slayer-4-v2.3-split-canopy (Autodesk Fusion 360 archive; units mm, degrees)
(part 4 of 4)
sketch "GEMFAN" plane through (28.9566, 10, -18.6867) normal (0, 1, 0) x axis (1, 0, 0)
  line L1 (-18.7002, -15.1005) -> (-18.9977, -15.145)
  curve K1 (-18.6889, -15.209) -> (-18.7002, -15.1005)
  curve K2 (-18.5682, -15.2594) -> (-18.6889, -15.209)
  curve K3 (-18.4588, -15.2187) -> (-18.5682, -15.2594)
  curve K4 (-18.4051, -15.1417) -> (-18.4588, -15.2187)
  curve K5 (-18.4216, -15.0733) -> (-18.4051, -15.1417)
  curve K6 (-18.5646, -15.0277) -> (-18.4216, -15.0733)
  curve K7 (-18.8229, -14.9284) -> (-18.5646, -15.0277)
  curve K8 (-18.8613, -14.738) -> (-18.8229, -14.9284)
  curve K9 (-18.7802, -14.5847) -> (-18.8613, -14.738)
  curve K10 (-18.6193, -14.4624) -> (-18.7802, -14.5847)
  curve K11 (-18.3644, -14.4007) -> (-18.6193, -14.4624)
  curve K12 (-18.0912, -14.4484) -> (-18.3644, -14.4007)
  curve K13 (-18.0289, -14.6706) -> (-18.0912, -14.4484)
  line L2 (-18.3234, -14.7135) -> (-18.0289, -14.6706)
  curve K14 (-18.3473, -14.617) -> (-18.3234, -14.7135)
  curve K15 (-18.4418, -14.5944) -> (-18.3473, -14.617)
  curve K16 (-18.5284, -14.625) -> (-18.4418, -14.5944)
  curve K17 (-18.5696, -14.6844) -> (-18.5284, -14.625)
  curve K18 (-18.558, -14.7265) -> (-18.5696, -14.6844)
  curve K19 (-18.4639, -14.7552) -> (-18.558, -14.7265)
  curve K20 (-18.197, -14.8206) -> (-18.4639, -14.7552)
  curve K21 (-18.0978, -14.9231) -> (-18.197, -14.8206)
  curve K22 (-18.0953, -15.0715) -> (-18.0978, -14.9231)
  curve K23 (-18.1929, -15.2581) -> (-18.0953, -15.0715)
  curve K24 (-18.3719, -15.3973) -> (-18.1929, -15.2581)
  curve K25 (-18.6224, -15.4614) -> (-18.3719, -15.3973)
  curve K26 (-18.9497, -15.3914) -> (-18.6224, -15.4614)
  curve K27 (-18.9977, -15.145) -> (-18.9497, -15.3914)
  line L3 (-17.4629, -14.339) -> (-17.7707, -14.3659)
  line L4 (-17.6524, -15.1122) -> (-17.4629, -14.339)
  line L5 (-17.172, -15.0702) -> (-17.6524, -15.1122)
  line L6 (-17.2339, -15.3228) -> (-17.172, -15.0702)
  line L7 (-18.0221, -15.3917) -> (-17.2339, -15.3228)
  line L8 (-17.7707, -14.3659) -> (-18.0221, -15.3917)
  line L9 (-16.7894, -15.1182) -> (-16.4399, -15.0876)
  line L10 (-16.8795, -15.2918) -> (-16.7894, -15.1182)
  line L11 (-17.1938, -15.3193) -> (-16.8795, -15.2918)
  line L12 (-16.568, -14.2607) -> (-17.1938, -15.3193)
  line L13 (-16.2322, -14.2313) -> (-16.568, -14.2607)
  line L14 (-16.1092, -15.2244) -> (-16.2322, -14.2313)
  line L15 (-16.4316, -15.2526) -> (-16.1092, -15.2244)
  line L16 (-16.4399, -15.0876) -> (-16.4316, -15.2526)
  line L17 (-16.469, -14.5122) -> (-16.4494, -14.8714)
  line L18 (-16.6682, -14.8905) -> (-16.469, -14.5122)
  line L19 (-16.4494, -14.8714) -> (-16.6682, -14.8905)
  line L20 (-15.6369, -14.1792) -> (-15.9788, -14.2091)
  line L21 (-15.521, -14.5077) -> (-15.6369, -14.1792)
  line L22 (-15.235, -14.1441) -> (-15.521, -14.5077)
  line L23 (-14.895, -14.1143) -> (-15.235, -14.1441)
  line L24 (-15.4284, -14.7444) -> (-14.895, -14.1143)
  line L25 (-15.5337, -15.174) -> (-15.4284, -14.7444)
  line L26 (-15.8422, -15.201) -> (-15.5337, -15.174)
  line L27 (-15.7369, -14.7714) -> (-15.8422, -15.201)
  line L28 (-15.9788, -14.2091) -> (-15.7369, -14.7714)
  line L29 (-13.9715, -14.0335) -> (-14.7964, -14.1057)
  line L30 (-14.0251, -14.2525) -> (-13.9715, -14.0335)
  line L31 (-14.5416, -14.2977) -> (-14.0251, -14.2525)
  line L32 (-14.5815, -14.4608) -> (-14.5416, -14.2977)
  line L33 (-14.1025, -14.4188) -> (-14.5815, -14.4608)
  line L34 (-14.1537, -14.6281) -> (-14.1025, -14.4188)
  line L35 (-14.6328, -14.67) -> (-14.1537, -14.6281)
  line L36 (-14.6824, -14.8722) -> (-14.6328, -14.67)
  line L37 (-14.151, -14.8257) -> (-14.6824, -14.8722)
  line L38 (-14.2079, -15.058) -> (-14.151, -14.8257)
  line L39 (-15.0478, -15.1315) -> (-14.2079, -15.058)
  line L40 (-14.7964, -14.1057) -> (-15.0478, -15.1315)
  line L41 (-13.7866, -14.0173) -> (-14.038, -15.0432)
  line L42 (-13.2736, -13.9725) -> (-13.7866, -14.0173)
  curve K28 (-13.0616, -13.9786) -> (-13.2736, -13.9725)
  curve K29 (-12.9629, -14.0613) -> (-13.0616, -13.9786)
  curve K30 (-12.9574, -14.2235) -> (-12.9629, -14.0613)
  curve K31 (-13.0289, -14.3739) -> (-12.9574, -14.2235)
  curve K32 (-13.1507, -14.4828) -> (-13.0289, -14.3739)
  curve K33 (-13.2688, -14.5328) -> (-13.1507, -14.4828)
  curve K34 (-13.1979, -14.5636) -> (-13.2688, -14.5328)
  curve K35 (-13.1619, -14.6133) -> (-13.1979, -14.5636)
  curve K36 (-13.1344, -14.6732) -> (-13.1619, -14.6133)
  line L43 (-13.0581, -14.9574) -> (-13.1344, -14.6732)
  line L44 (-13.406, -14.9879) -> (-13.0581, -14.9574)
  line L45 (-13.4937, -14.6888) -> (-13.406, -14.9879)
  curve K37 (-13.53, -14.6146) -> (-13.4937, -14.6888)
  curve K38 (-13.5996, -14.5974) -> (-13.53, -14.6146)
  line L46 (-13.6268, -14.5998) -> (-13.5996, -14.5974)
  line L47 (-13.7288, -15.0161) -> (-13.6268, -14.5998)
  line L48 (-14.038, -15.0432) -> (-13.7288, -15.0161)
  line L49 (-13.4495, -14.3946) -> (-13.5793, -14.4059)
  curve K39 (-13.3645, -14.3735) -> (-13.4495, -14.3946)
  curve K40 (-13.3067, -14.3369) -> (-13.3645, -14.3735)
  curve K41 (-13.2728, -14.2757) -> (-13.3067, -14.3369)
  curve K42 (-13.2847, -14.2021) -> (-13.2728, -14.2757)
  curve K43 (-13.393, -14.1856) -> (-13.2847, -14.2021)
  line L50 (-13.5282, -14.1974) -> (-13.393, -14.1856)
  line L51 (-13.5793, -14.4059) -> (-13.5282, -14.1974)
  line L52 (-11.9458, -13.8563) -> (-12.7069, -13.9229)
  line L53 (-11.9998, -14.0767) -> (-11.9458, -13.8563)
  line L54 (-12.4517, -14.1162) -> (-11.9998, -14.0767)
  line L55 (-12.4956, -14.2954) -> (-12.4517, -14.1162)
  line L56 (-12.1096, -14.2616) -> (-12.4956, -14.2954)
  line L57 (-12.1604, -14.4687) -> (-12.1096, -14.2616)
  line L58 (-12.5464, -14.5025) -> (-12.1604, -14.4687)
  line L59 (-12.6491, -14.9216) -> (-12.5464, -14.5025)
  line L60 (-12.9583, -14.9487) -> (-12.6491, -14.9216)
  line L61 (-12.7069, -13.9229) -> (-12.9583, -14.9487)
  line L62 (-11.858, -14.6867) -> (-11.5086, -14.6562)
  line L63 (-11.9481, -14.8603) -> (-11.858, -14.6867)
  line L64 (-12.2624, -14.8878) -> (-11.9481, -14.8603)
  line L65 (-11.6366, -13.8292) -> (-12.2624, -14.8878)
  line L66 (-11.3008, -13.7999) -> (-11.6366, -13.8292)
  line L67 (-11.1779, -14.7929) -> (-11.3008, -13.7999)
  line L68 (-11.5002, -14.8211) -> (-11.1779, -14.7929)
  line L69 (-11.5086, -14.6562) -> (-11.5002, -14.8211)
  line L70 (-11.5376, -14.0808) -> (-11.5181, -14.4399)
  line L71 (-11.7368, -14.4591) -> (-11.5376, -14.0808)
  line L72 (-11.5181, -14.4399) -> (-11.7368, -14.4591)
  line L73 (-10.5391, -13.7332) -> (-10.8266, -13.7584)
  line L74 (-10.3031, -14.2679) -> (-10.5391, -13.7332)
  line L75 (-10.164, -13.7004) -> (-10.3031, -14.2679)
  line L76 (-9.8739, -13.675) -> (-10.164, -13.7004)
  line L77 (-10.1253, -14.7008) -> (-9.8739, -13.675)
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extrude "Extrude4" sketch "GEMFAN" blind 0.1 named "d44"
sketch "Sketch13" plane through (0, 10, 0) normal (0, 1, 0) x axis (1, 0, 0)
  line L1 (-2.5624, -10.9882) -> (-2.8879, -10.8364)
  line L2 (-2.2874, -10.3984) -> (-2.5624, -10.9882)
  line L3 (-2.1344, -10.4698) -> (-2.2874, -10.3984)
  line L4 (-1.5427, -11.501) -> (-2.1344, -10.4698)
  line L5 (-1.6063, -11.6373) -> (-1.5427, -11.501)
  line L6 (-2.4872, -11.2265) -> (-1.6063, -11.6373)
  line L7 (-2.5728, -11.4101) -> (-2.4872, -11.2265)
  line L8 (-2.7258, -11.3388) -> (-2.5728, -11.4101)
  line L9 (-2.6402, -11.1551) -> (-2.7258, -11.3388)
  line L10 (-2.9657, -11.0034) -> (-2.6402, -11.1551)
  line L11 (-2.8879, -10.8364) -> (-2.9657, -11.0034)
  line L12 (-1.7964, -11.3454) -> (-2.4094, -11.0596)
  line L13 (-2.2109, -10.6339) -> (-1.7964, -11.3454)
  line L14 (-2.4094, -11.0596) -> (-2.2109, -10.6339)
  curve K1 (-2.0955, -11.9008) -> (-2.4604, -11.6702)
  curve K2 (-1.9375, -12.154) -> (-2.0955, -11.9008)
  curve K3 (-1.9726, -12.4374) -> (-1.9375, -12.154)
  curve K4 (-2.1061, -12.6088) -> (-1.9726, -12.4374)
  curve K5 (-2.2967, -12.6859) -> (-2.1061, -12.6088)
  curve K6 (-2.5383, -12.676) -> (-2.2967, -12.6859)
  curve K7 (-2.8738, -12.5568) -> (-2.5383, -12.676)
  curve K8 (-3.2372, -12.3275) -> (-2.8738, -12.5568)
  curve K9 (-3.3958, -12.0746) -> (-3.2372, -12.3275)
  curve K10 (-3.3608, -11.7901) -> (-3.3958, -12.0746)
  curve K11 (-3.0758, -11.547) -> (-3.3608, -11.7901)
  curve K12 (-2.4604, -11.6702) -> (-3.0758, -11.547)
  curve K13 (-3.0226, -11.7124) -> (-2.5404, -11.8418)
  curve K14 (-3.2235, -11.8541) -> (-3.0226, -11.7124)
  curve K15 (-3.2024, -12.0993) -> (-3.2235, -11.8541)
  curve K16 (-2.7938, -12.3852) -> (-3.2024, -12.0993)
  curve K17 (-2.3113, -12.5148) -> (-2.7938, -12.3852)
  curve K18 (-2.1099, -12.3711) -> (-2.3113, -12.5148)
  curve K19 (-2.1216, -12.1421) -> (-2.1099, -12.3711)
  curve K20 (-2.5404, -11.8418) -> (-2.1216, -12.1421)
  line L15 (-3.5474, -13.1007) -> (-3.8729, -12.9489)
  line L16 (-3.2724, -12.5109) -> (-3.5474, -13.1007)
  line L17 (-3.1194, -12.5822) -> (-3.2724, -12.5109)
  line L18 (-2.5277, -13.6134) -> (-3.1194, -12.5822)
  line L19 (-2.5913, -13.7497) -> (-2.5277, -13.6134)
  line L20 (-3.4723, -13.3389) -> (-2.5913, -13.7497)
  line L21 (-3.5579, -13.5226) -> (-3.4723, -13.3389)
  line L22 (-3.7109, -13.4512) -> (-3.5579, -13.5226)
  line L23 (-3.6253, -13.2676) -> (-3.7109, -13.4512)
  line L24 (-3.9508, -13.1158) -> (-3.6253, -13.2676)
  line L25 (-3.8729, -12.9489) -> (-3.9508, -13.1158)
  line L26 (-2.7815, -13.4579) -> (-3.3944, -13.172)
  line L27 (-3.196, -12.7464) -> (-2.7815, -13.4579)
  line L28 (-3.3944, -13.172) -> (-3.196, -12.7464)
  curve K21 (-3.0805, -14.0133) -> (-3.4455, -13.7827)
  curve K22 (-2.9226, -14.2664) -> (-3.0805, -14.0133)
  curve K23 (-2.9576, -14.5498) -> (-2.9226, -14.2664)
  curve K24 (-3.0912, -14.7213) -> (-2.9576, -14.5498)
  curve K25 (-3.2818, -14.7983) -> (-3.0912, -14.7213)
  curve K26 (-3.5233, -14.7885) -> (-3.2818, -14.7983)
  curve K27 (-3.8589, -14.6692) -> (-3.5233, -14.7885)
  curve K28 (-4.2222, -14.44) -> (-3.8589, -14.6692)
  curve K29 (-4.3809, -14.187) -> (-4.2222, -14.44)
  curve K30 (-4.3458, -13.9025) -> (-4.3809, -14.187)
  curve K31 (-4.0609, -13.6594) -> (-4.3458, -13.9025)
  curve K32 (-3.4455, -13.7827) -> (-4.0609, -13.6594)
  curve K33 (-4.0076, -13.8248) -> (-3.5255, -13.9543)
  curve K34 (-4.2086, -13.9665) -> (-4.0076, -13.8248)
  curve K35 (-4.1875, -14.2117) -> (-4.2086, -13.9665)
  curve K36 (-3.7789, -14.4977) -> (-4.1875, -14.2117)
  curve K37 (-3.2963, -14.6273) -> (-3.7789, -14.4977)
  curve K38 (-3.0949, -14.4836) -> (-3.2963, -14.6273)
  curve K39 (-3.1067, -14.2545) -> (-3.0949, -14.4836)
  curve K40 (-3.5255, -13.9543) -> (-3.1067, -14.2545)
extrude "Extrude6" sketch "Sketch13" blind 0.1 (= "d44")
work_plane "WorkPlane9" AlongDistance -24
sketch "GEMFAN (1)" plane through (28.9566, -14, -18.6867) normal (0, 1, 0) x axis (1, 0, 0)
  line L1 (-10.4908, -14.3859) -> (-10.1901, -14.3781)
  curve K1 (-10.483, -14.4948) -> (-10.4908, -14.3859)
  curve K2 (-10.5931, -14.5653) -> (-10.483, -14.4948)
  curve K3 (-10.7079, -14.5442) -> (-10.5931, -14.5653)
  curve K4 (-10.7742, -14.4778) -> (-10.7079, -14.5442)
  curve K5 (-10.7699, -14.4076) -> (-10.7742, -14.4778)
  curve K6 (-10.6369, -14.3377) -> (-10.7699, -14.4076)
  curve K7 (-10.3998, -14.1951) -> (-10.6369, -14.3377)
  curve K8 (-10.395, -14.0009) -> (-10.3998, -14.1951)
  curve K9 (-10.5015, -13.864) -> (-10.395, -14.0009)
  curve K10 (-10.6812, -13.7716) -> (-10.5015, -13.864)
  curve K11 (-10.9429, -13.7551) -> (-10.6812, -13.7716)
  curve K12 (-11.2037, -13.8495) -> (-10.9429, -13.7551)
  curve K13 (-11.2265, -14.0791) -> (-11.2037, -13.8495)
  line L2 (-10.929, -14.0702) -> (-11.2265, -14.0791)
  curve K14 (-10.9223, -13.971) -> (-10.929, -14.0702)
  curve K15 (-10.8331, -13.9324) -> (-10.9223, -13.971)
  curve K16 (-10.7425, -13.9474) -> (-10.8331, -13.9324)
  curve K17 (-10.6916, -13.9988) -> (-10.7425, -13.9474)
  curve K18 (-10.6957, -14.0423) -> (-10.6916, -13.9988)
  curve K19 (-10.7834, -14.0869) -> (-10.6957, -14.0423)
  curve K20 (-11.0349, -14.1976) -> (-10.7834, -14.0869)
  curve K21 (-11.1148, -14.3159) -> (-11.0349, -14.1976)
  curve K22 (-11.0915, -14.4624) -> (-11.1148, -14.3159)
  curve K23 (-10.963, -14.6292) -> (-11.0915, -14.4624)
  curve K24 (-10.7625, -14.7352) -> (-10.963, -14.6292)
  curve K25 (-10.5047, -14.7548) -> (-10.7625, -14.7352)
  curve K26 (-10.1945, -14.6291) -> (-10.5047, -14.7548)
  curve K27 (-10.1901, -14.3781) -> (-10.1945, -14.6291)
  line L3 (-11.8415, -13.8508) -> (-11.5336, -13.8239)
  line L4 (-11.5206, -14.5794) -> (-11.8415, -13.8508)
  line L5 (-12.001, -14.6214) -> (-11.5206, -14.5794)
  line L6 (-11.8962, -14.8594) -> (-12.001, -14.6214)
  line L7 (-11.1079, -14.7905) -> (-11.8962, -14.8594)
  line L8 (-11.5336, -13.8239) -> (-11.1079, -14.7905)
  line L9 (-12.3694, -14.7351) -> (-12.7189, -14.7657)
  line L10 (-12.2506, -14.8904) -> (-12.3694, -14.7351)
  line L11 (-11.9363, -14.8629) -> (-12.2506, -14.8904)
  line L12 (-12.7364, -13.9291) -> (-11.9363, -14.8629)
  line L13 (-13.0722, -13.9585) -> (-12.7364, -13.9291)
  line L14 (-13.0208, -14.9578) -> (-13.0722, -13.9585)
  line L15 (-12.6985, -14.9296) -> (-13.0208, -14.9578)
  line L16 (-12.7189, -14.7657) -> (-12.6985, -14.9296)
  line L17 (-12.7902, -14.194) -> (-12.7471, -14.5511)
  line L18 (-12.5283, -14.532) -> (-12.7902, -14.194)
  line L19 (-12.7471, -14.5511) -> (-12.5283, -14.532)
  line L20 (-13.6675, -14.0106) -> (-13.3256, -13.9807)
  line L21 (-13.7246, -14.3542) -> (-13.6675, -14.0106)
  line L22 (-14.0693, -14.0457) -> (-13.7246, -14.3542)
  line L23 (-14.4094, -14.0755) -> (-14.0693, -14.0457)
  line L24 (-13.7747, -14.6033) -> (-14.4094, -14.0755)
  line L25 (-13.5964, -15.0082) -> (-13.7747, -14.6033)
  line L26 (-13.2879, -14.9812) -> (-13.5964, -15.0082)
  line L27 (-13.4662, -14.5764) -> (-13.2879, -14.9812)
  line L28 (-13.3256, -13.9807) -> (-13.4662, -14.5764)
  line L29 (-15.3329, -14.1563) -> (-14.508, -14.0841)
  line L30 (-15.242, -14.3627) -> (-15.3329, -14.1563)
  line L31 (-14.7256, -14.3175) -> (-15.242, -14.3627)
  line L32 (-14.6579, -14.4711) -> (-14.7256, -14.3175)
  line L33 (-15.137, -14.513) -> (-14.6579, -14.4711)
  line L34 (-15.0502, -14.7101) -> (-15.137, -14.513)
  line L35 (-14.5711, -14.6682) -> (-15.0502, -14.7101)
  line L36 (-14.4872, -14.8588) -> (-14.5711, -14.6682)
  line L37 (-15.0186, -14.9053) -> (-14.4872, -14.8588)
  line L38 (-14.9221, -15.1242) -> (-15.0186, -14.9053)
  line L39 (-14.0822, -15.0507) -> (-14.9221, -15.1242)
  line L40 (-14.508, -14.0841) -> (-14.0822, -15.0507)
  line L41 (-15.5177, -14.1725) -> (-15.092, -15.139)
  line L42 (-16.0308, -14.2173) -> (-15.5177, -14.1725)
  curve K28 (-16.2385, -14.2602) -> (-16.0308, -14.2173)
  curve K29 (-16.3213, -14.3588) -> (-16.2385, -14.2602)
  curve K30 (-16.2986, -14.5195) -> (-16.3213, -14.3588)
  curve K31 (-16.2021, -14.6551) -> (-16.2986, -14.5195)
  curve K32 (-16.0632, -14.7413) -> (-16.2021, -14.6551)
  curve K33 (-15.9382, -14.77) -> (-16.0632, -14.7413)
  curve K34 (-16.0027, -14.8127) -> (-15.9382, -14.77)
  curve K35 (-16.0295, -14.8678) -> (-16.0027, -14.8127)
  curve K36 (-16.0462, -14.9316) -> (-16.0295, -14.8678)
  line L43 (-16.0719, -15.2248) -> (-16.0462, -14.9316)
  line L44 (-15.7241, -15.1943) -> (-16.0719, -15.2248)
  line L45 (-15.6896, -14.8846) -> (-15.7241, -15.1943)
  curve K37 (-15.6667, -14.8052) -> (-15.6896, -14.8846)
  curve K38 (-15.6012, -14.7762) -> (-15.6667, -14.8052)
  line L46 (-15.574, -14.7738) -> (-15.6012, -14.7762)
  line L47 (-15.4012, -15.1661) -> (-15.574, -14.7738)
  line L48 (-15.092, -15.139) -> (-15.4012, -15.1661)
  line L49 (-15.7842, -14.6025) -> (-15.6544, -14.5911)
  curve K39 (-15.8716, -14.5964) -> (-15.7842, -14.6025)
  curve K40 (-15.9349, -14.5705) -> (-15.8716, -14.5964)
  curve K41 (-15.9789, -14.5161) -> (-15.9349, -14.5705)
  curve K42 (-15.98, -14.4416) -> (-15.9789, -14.5161)
  curve K43 (-15.8762, -14.4065) -> (-15.98, -14.4416)
  line L50 (-15.741, -14.3947) -> (-15.8762, -14.4065)
  line L51 (-15.6544, -14.5911) -> (-15.741, -14.3947)
  line L52 (-17.3586, -14.3335) -> (-16.5975, -14.2669)
  line L53 (-17.2671, -14.5412) -> (-17.3586, -14.3335)
  line L54 (-16.8152, -14.5017) -> (-17.2671, -14.5412)
  line L55 (-16.7409, -14.6704) -> (-16.8152, -14.5017)
  line L56 (-17.1269, -14.7042) -> (-16.7409, -14.6704)
  line L57 (-17.0409, -14.8994) -> (-17.1269, -14.7042)
  line L58 (-16.6549, -14.8656) -> (-17.0409, -14.8994)
  line L59 (-16.481, -15.2605) -> (-16.6549, -14.8656)
  line L60 (-16.1718, -15.2335) -> (-16.481, -15.2605)
  line L61 (-16.5975, -14.2669) -> (-16.1718, -15.2335)
  line L62 (-17.3008, -15.1666) -> (-17.6503, -15.1971)
  line L63 (-17.182, -15.3219) -> (-17.3008, -15.1666)
  line L64 (-16.8677, -15.2944) -> (-17.182, -15.3219)
  line L65 (-17.6678, -14.3606) -> (-16.8677, -15.2944)
  line L66 (-18.0036, -14.3899) -> (-17.6678, -14.3606)
  line L67 (-17.9522, -15.3893) -> (-18.0036, -14.3899)
  line L68 (-17.6298, -15.3611) -> (-17.9522, -15.3893)
  line L69 (-17.6503, -15.1971) -> (-17.6298, -15.3611)
  line L70 (-17.7215, -14.6255) -> (-17.6785, -14.9825)
  line L71 (-17.4597, -14.9634) -> (-17.7215, -14.6255)
  line L72 (-17.6785, -14.9825) -> (-17.4597, -14.9634)
  line L73 (-18.7652, -14.4566) -> (-18.4778, -14.4314)
  line L74 (-18.9048, -15.0241) -> (-18.7652, -14.4566)
  line L75 (-19.1403, -14.4894) -> (-18.9048, -15.0241)
  line L76 (-19.4305, -14.5148) -> (-19.1403, -14.4894)
  line L77 (-19.0048, -15.4813) -> (-19.4305, -14.5148)
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sketch "4040R" plane through (28.9566, -14, -18.6867) normal (0, 1, 0) x axis (1, 0, 0)
  line L1 (-33.0077, -32.8191) -> (-33.3332, -32.6673)
  line L2 (-33.2827, -33.4089) -> (-33.0077, -32.8191)
  line L3 (-33.1297, -33.4803) -> (-33.2827, -33.4089)
  line L4 (-31.9595, -33.2707) -> (-33.1297, -33.4803)
  line L5 (-31.8959, -33.1344) -> (-31.9595, -33.2707)
  line L6 (-32.7768, -32.7236) -> (-31.8959, -33.1344)
  line L7 (-32.6912, -32.5399) -> (-32.7768, -32.7236)
  line L8 (-32.8442, -32.4686) -> (-32.6912, -32.5399)
  line L9 (-32.9299, -32.6522) -> (-32.8442, -32.4686)
  line L10 (-33.2553, -32.5004) -> (-32.9299, -32.6522)
  line L11 (-33.3332, -32.6673) -> (-33.2553, -32.5004)
  line L12 (-32.2417, -33.1763) -> (-32.8547, -32.8905)
  line L13 (-33.0532, -33.3161) -> (-32.2417, -33.1763)
  line L14 (-32.8547, -32.8905) -> (-33.0532, -33.3161)
  curve K1 (-32.0085, -32.5902) -> (-32.4197, -32.4588)
  curve K2 (-31.713, -32.5485) -> (-32.0085, -32.5902)
  curve K3 (-31.5184, -32.3394) -> (-31.713, -32.5485)
  curve K4 (-31.473, -32.127) -> (-31.5184, -32.3394)
  curve K5 (-31.5365, -31.9314) -> (-31.473, -32.127)
  curve K6 (-31.6993, -31.7527) -> (-31.5365, -31.9314)
  curve K7 (-32.0063, -31.5723) -> (-31.6993, -31.7527)
  curve K8 (-32.4155, -31.4414) -> (-32.0063, -31.5723)
  curve K9 (-32.7112, -31.4824) -> (-32.4155, -31.4414)
  curve K10 (-32.9067, -31.6921) -> (-32.7112, -31.4824)
  curve K11 (-32.9097, -32.0666) -> (-32.9067, -31.6921)
  curve K12 (-32.4197, -32.4588) -> (-32.9097, -32.0666)
  curve K13 (-32.7487, -32.0011) -> (-32.3397, -32.2873)
  curve K14 (-32.7694, -31.7561) -> (-32.7487, -32.0011)
  curve K15 (-32.568, -31.6147) -> (-32.7694, -31.7561)
  curve K16 (-32.0863, -31.7439) -> (-32.568, -31.6147)
  curve K17 (-31.6768, -32.0302) -> (-32.0863, -31.7439)
  curve K18 (-31.6575, -32.2769) -> (-31.6768, -32.0302)
  curve K19 (-31.8405, -32.4151) -> (-31.6575, -32.2769)
  curve K20 (-32.3397, -32.2873) -> (-31.8405, -32.4151)
  line L15 (-32.0226, -30.7067) -> (-32.3481, -30.5549)
  line L16 (-32.2977, -31.2965) -> (-32.0226, -30.7067)
  line L17 (-32.1446, -31.3678) -> (-32.2977, -31.2965)
  line L18 (-30.9744, -31.1582) -> (-32.1446, -31.3678)
  line L19 (-30.9108, -31.0219) -> (-30.9744, -31.1582)
  line L20 (-31.7918, -30.6111) -> (-30.9108, -31.0219)
  line L21 (-31.7062, -30.4275) -> (-31.7918, -30.6111)
  line L22 (-31.8592, -30.3561) -> (-31.7062, -30.4275)
  line L23 (-31.9448, -30.5398) -> (-31.8592, -30.3561)
  line L24 (-32.2703, -30.388) -> (-31.9448, -30.5398)
  line L25 (-32.3481, -30.5549) -> (-32.2703, -30.388)
  line L26 (-31.2567, -31.0639) -> (-31.8696, -30.778)
  line L27 (-32.0681, -31.2037) -> (-31.2567, -31.0639)
  line L28 (-31.8696, -30.778) -> (-32.0681, -31.2037)
  curve K21 (-31.0234, -30.4777) -> (-31.4347, -30.3464)
  curve K22 (-30.7279, -30.436) -> (-31.0234, -30.4777)
  curve K23 (-30.5334, -30.227) -> (-30.7279, -30.436)
  curve K24 (-30.4879, -30.0145) -> (-30.5334, -30.227)
  curve K25 (-30.5514, -29.8189) -> (-30.4879, -30.0145)
  curve K26 (-30.7142, -29.6403) -> (-30.5514, -29.8189)
  curve K27 (-31.0213, -29.4599) -> (-30.7142, -29.6403)
  curve K28 (-31.4304, -29.3289) -> (-31.0213, -29.4599)
  curve K29 (-31.7261, -29.3699) -> (-31.4304, -29.3289)
  curve K30 (-31.9216, -29.5797) -> (-31.7261, -29.3699)
  curve K31 (-31.9246, -29.9542) -> (-31.9216, -29.5797)
  curve K32 (-31.4347, -30.3464) -> (-31.9246, -29.9542)
  curve K33 (-31.7637, -29.8887) -> (-31.3547, -30.1748)
  curve K34 (-31.7844, -29.6437) -> (-31.7637, -29.8887)
  curve K35 (-31.5829, -29.5022) -> (-31.7844, -29.6437)
  curve K36 (-31.1013, -29.6314) -> (-31.5829, -29.5022)
  curve K37 (-30.6918, -29.9178) -> (-31.1013, -29.6314)
  curve K38 (-30.6724, -30.1644) -> (-30.6918, -29.9178)
  curve K39 (-30.8554, -30.3026) -> (-30.6724, -30.1644)
  curve K40 (-31.3547, -30.1748) -> (-30.8554, -30.3026)
  line L29 (-30.2203, -29.541) -> (-31.5797, -28.907)
  line L30 (-29.9392, -28.9382) -> (-30.2203, -29.541)
  curve K41 (-29.847, -28.6448) -> (-29.9392, -28.9382)
  curve K42 (-29.9058, -28.4333) -> (-29.847, -28.6448)
  curve K43 (-30.0844, -28.2812) -> (-29.9058, -28.4333)
  curve K44 (-30.372, -28.2611) -> (-30.0844, -28.2812)
  curve K45 (-30.633, -28.4916) -> (-30.372, -28.2611)
  curve K46 (-30.6501, -28.3516) -> (-30.633, -28.4916)
  curve K47 (-30.7613, -28.1179) -> (-30.6501, -28.3516)
  line L31 (-31.021, -27.7089) -> (-30.7613, -28.1179)
  line L32 (-31.1265, -27.9352) -> (-31.021, -27.7089)
  line L33 (-30.9276, -28.247) -> (-31.1265, -27.9352)
  curve K48 (-30.8008, -28.4642) -> (-30.9276, -28.247)
  curve K49 (-30.7525, -28.5979) -> (-30.8008, -28.4642)
  curve K50 (-30.7546, -28.6968) -> (-30.7525, -28.5979)
  curve K51 (-30.7948, -28.8) -> (-30.7546, -28.6968)
  line L34 (-30.8921, -29.0086) -> (-30.7948, -28.8)
  line L35 (-31.4958, -28.7271) -> (-30.8921, -29.0086)
  line L36 (-31.5797, -28.907) -> (-31.4958, -28.7271)
  line L37 (-30.556, -28.6946) -> (-30.7364, -29.0813)
  curve K52 (-30.4406, -28.5136) -> (-30.556, -28.6946)
  curve K53 (-30.3097, -28.4459) -> (-30.4406, -28.5136)
  curve K54 (-30.1709, -28.4666) -> (-30.3097, -28.4459)
  curve K55 (-30.045, -28.6106) -> (-30.1709, -28.4666)
  curve K56 (-30.086, -28.8607) -> (-30.045, -28.6106)
  line L38 (-30.2866, -29.291) -> (-30.086, -28.8607)
  line L39 (-30.7364, -29.0813) -> (-30.2866, -29.291)
extrude "Extrude10" sketch "GEMFAN (1)" blind -0.1 (= "-d44")
extrude "Extrude8" sketch "4040R" blind -0.1 (= "-d44")
component_from_bodies "Body->Comp1"
component_from_bodies "Body->Comp2"
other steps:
base_feature "Base Feature1" bodies "CW Prop"
base_feature "Base Feature1" bodies "CCW Prop"
create_component "CreateComponent1"
create_component "CreateComponent2"
remove_body "RemoveBody2"
remove_body "RemoveBody3"
named bodies: "CW Prop", "CCW Prop"

design "runcam_phoenix_2"
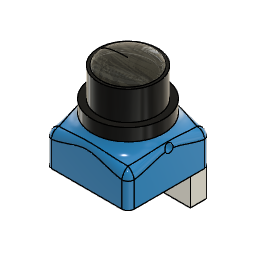
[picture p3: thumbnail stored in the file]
sketch "Skizze1" plane through (0, 0, 0) normal (0, 0, 1) x axis (1, 0, 0)
  line L1 (20, 0) -> (0, 0)
  line L2 (20, 20) -> (20, 0)
  line L3 (0, 20) -> (20, 20)
  line L4 (0, 0) -> (0, 20)
  point P1 (0, 0)
  point P2 (0, 0)
  point P3 (20, 0)
  point P5 (0, 20)
  horizontal L1
  vertical L2
  horizontal L3
  vertical L4
  coincident P1 P2
  dimension "d1" distance P2 P3 = 20
  dimension "d2" distance P2 P5 = 20
extrude "Extrusion1" new body sketch "Skizze1" along normal blind 8
sketch "Skizze2" plane through (0, 0, 8) normal (0, 0, 1) x axis (-1, 0, 0)
  line L1 (0, 0) -> (0, -20)
  line L2 (-20, 0) -> (0, 0)
  line L3 (-20, -20) -> (-20, 0)
  line L4 (0, -20) -> (-20, -20)
  circle C1 centre (-10, -10) radius 8.15
  dimension "d5" diameter C1 = 16.3
extrude "Extrusion2" add sketch "Skizze2" profile of C1 along normal blind 13
fillet "Abrundung1" radius 1.5
fillet "Abrundung2" radius 5
fillet "Abrundung3" radius 2
sphere_primitive "Grundkörper Kugel" Diameter 13
scale "Maßstab" ScaleZ 0.2475
split "Teilen1"
work_plane "Arbeitsebene" AlongDistance -13
split "Teilen2"
sketch "Skizze4" plane through (20, 0, 0) normal (1, 0, 0) x axis (0, 1, 0)
  curve K1 (18.5, 6.1577) -> (1.5, 6.1577)
  line L1 (1.5, 0) -> (1.5, 6.1577)
  line L2 (18.5, 0) -> (1.5, 0)
  line L3 (18.5, 6.1577) -> (18.5, 0)
  circle C1 centre (10, 8.5) radius 0.975
  point P6 (10, 8.5)
  dimension "d19" diameter C1 = 1.95
  dimension "d20" distance L2 P6 = 8.5
extrude "Extrusion3" cut sketch "Skizze4" profile of C1 against normal blind 4
sketch "Skizze5" plane through (0, 0, 0) normal (-1, 0, 0) x axis (0, -1, 0)
  curve K1 (-1.5, 6.1577) -> (-18.5, 6.1577)
  line L1 (-18.5, 0) -> (-18.5, 6.1577)
  line L2 (-1.5, 0) -> (-18.5, 0)
  line L3 (-1.5, 6.1577) -> (-1.5, 0)
  curve K2 (-10.9281, 8.2013) -> (-9.0719, 8.2013)
  arc A1 centre (-10, 8.5) radius 0.975 clockwise from (-9.0719, 8.2013) to (-10.9281, 8.2013)
extrude "Extrusion4" cut sketch "Skizze5" profile of A1 against normal blind 4
sketch "Skizze7" plane through (0, 0, 0) normal (0, 0, -1) x axis (1, 0, 0)
  line L1 (20, -1.5) -> (20, -18.5)
  line L2 (1.5, 0) -> (18.5, 0)
  line L3 (18.5, -20) -> (1.5, -20)
  line L4 (9.5607, -19.5607) -> (19.5607, -19.5607)
  line L5 (9.5607, -15.5607) -> (9.5607, -19.5607)
  line L6 (19.5607, -15.5607) -> (9.5607, -15.5607)
  line L7 (19.5607, -19.5607) -> (19.5607, -15.5607)
  line L8 (0, -18.5) -> (0, -1.5)
  arc A1 centre (18.5, -18.5) radius 1.5 clockwise from (20, -18.5) to (18.5, -20)
  arc A2 centre (18.5, -1.5) radius 1.5 clockwise from (18.5, 0) to (20, -1.5)
  arc A3 centre (1.5, -1.5) radius 1.5 clockwise from (0, -1.5) to (1.5, 0)
  arc A4 centre (1.5, -18.5) radius 1.5 clockwise from (1.5, -20) to (0, -18.5)
  point P14 (19.5607, -19.5607)
  point P15 (9.5607, -19.5607)
  point P17 (19.5607, -15.5607)
  horizontal L4
  vertical L5
  horizontal L6
  vertical L7
  midpoint A1 P14
  dimension "d25" distance P14 P15 = 10
  dimension "d26" distance P14 P17 = 4
extrude "Extrusion5" new body sketch "Skizze7" profile of L4 L5 L6 L7 along normal blind 7
work_plane "WorkPlane2" AlongDistance -6
split_face "SplitFace1"
offset_faces "OffsetFaces1" distance 1
extrude "Extrude6" add of existing geometry blind 2
extrude "Extrude7" cut of existing geometry blind -1
offset_faces "OffsetFaces2" distance -1
offset_faces "OffsetFaces3" distance -0.5

design "M2 x 0.4mm Thread 5mm LONG SOCKET HEAD CAP SCREW"
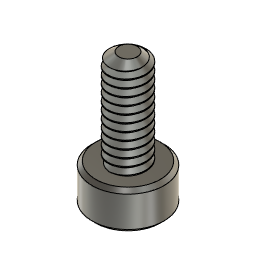
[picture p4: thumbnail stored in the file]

design "M3 x 0.5mm Thread 6mm LONG SOCKET HEAD CAP SCREW"
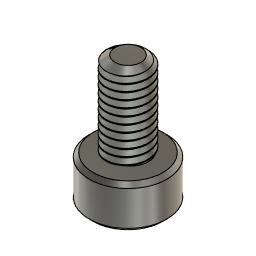
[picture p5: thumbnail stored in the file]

design "CADDXFPV Ratel 2.1mm"
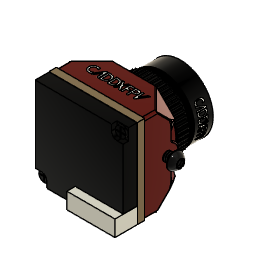
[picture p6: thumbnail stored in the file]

design "EACHINE CCW TYRO79-1607-2800KV"
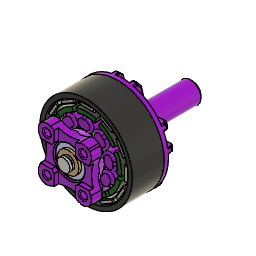
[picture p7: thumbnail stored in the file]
